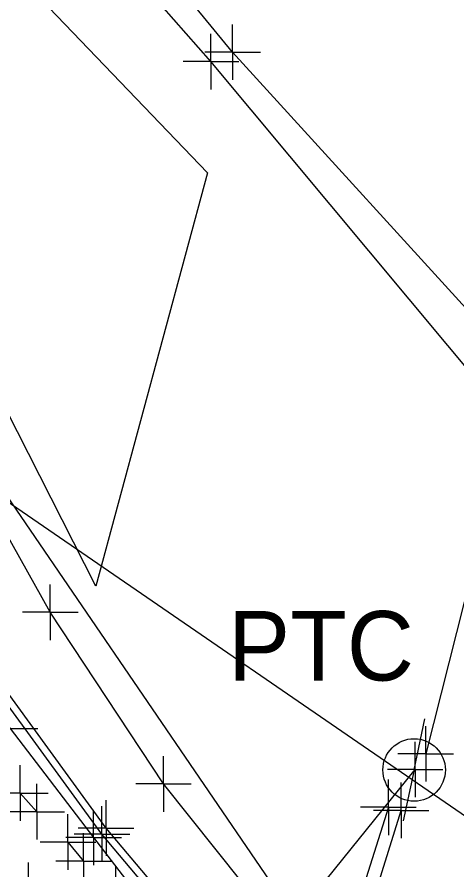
# Model space of a CAD drawing. Extents: x 0 to 1944463, y 0 to 420651.
# Drawn here: x 1943092.9 to 1943124.6, y 417632.9 to 417694.3 of the extents above; entities that cross this region are included whole.
import ezdxf

# ---------------------------------------------------------------- set-up
doc = ezdxf.new("R2010")
doc.units = 0
for name, color, linetype in [('SUR - DRG - Bridges', 7, 'Continuous'), ('SUR - DRG - Bridges - Points - Locators', 7, 'Continuous'), ('SUR - DRG - Storm Sewer', 7, 'Continuous'), ('SUR - DTM - Breaklines', 7, 'Continuous'), ('SUR - DTM - Breaklines - Points - Locators', 7, 'Continuous'), ('SUR - NON-TRAN - Features', 7, 'Continuous'), ('SUR - NON-TRAN - Features - Points - Locators', 7, 'Continuous'), ('SUR - TR-CTRL - Pavement Marking', 7, 'Continuous'), ('SUR - TR-CTRL - Pavement Marking - Points - Locators', 7, 'Continuous'), ('SUR - TRAN - Features', 7, 'Continuous'), ('SUR - TRAN - Features - Points - Locators', 7, 'Continuous'), ('SUR - UTL - Overhead Wire Crossings', 7, 'Continuous'), ('SUR - UTL - Overhead Wire Crossings - Points - Locators', 7, 'Continuous'), ('SUR - UTL - Poles and Miscellaneous', 7, 'Continuous'), ('SUR - UTL - Poles and Miscellaneous Text', 7, 'Continuous'), ('SUR - VEG - Features', 7, 'Continuous')]:
    doc.layers.add(name, color=color, linetype=linetype)

msp = doc.modelspace()

# ---------------------------------------------------------------- linework, layer by layer
at = {"layer": 'SUR - DRG - Bridges'}
msp.add_lwpolyline([(1943118.022, 417624.072), (1943118.566, 417626.015), (1943117.262, 417626.592), (1943120.565, 417637.227)], dxfattribs=at)
at = {"layer": 'SUR - DRG - Bridges - Points - Locators'}
for q in [(1943120.565, 417639.227), (1943118.565, 417637.227), (1943122.565, 417637.227), (1943120.565, 417635.227)]:
    msp.add_line((1943120.565, 417637.227), q, dxfattribs=at)
at = {"layer": 'SUR - DRG - Storm Sewer'}
msp.add_lwpolyline([(1942946.03, 417759.83), (1943172.9, 417604.06)], dxfattribs=at)
at = {"layer": 'SUR - DTM - Breaklines'}
for points in [[(1943113.816, 417618.747), (1943099.312, 417635.958), (1943090.009, 417648.721), (1943077.226, 417667.859), (1943069.186, 417677.24), (1943048.744, 417697.336), (1943014.67, 417728.445), (1942991.453, 417748.17), (1942972.688, 417763.041), (1942938.864, 417788.284), (1942937.547, 417790.234), (1942937.458, 417791.641), (1942938.043, 417793.096)], [(1943148.594, 417595.6), (1943148.623, 417618.666), (1943148.003, 417634.848), (1943135.154, 417656.915), (1943126.831, 417667.186), (1943106.868, 417691.105), (1943092.646, 417707.26), (1943066.336, 417736.048), (1943052.909, 417761.604)], [(1943088.753, 417664.788), (1943115.13, 417626.235)], [(1943119.642, 417637.454), (1943116.27, 417626.76), (1943116, 417625.717)]]:
    msp.add_lwpolyline(points, dxfattribs=at)
at = {"layer": 'SUR - DTM - Breaklines - Points - Locators'}
for p, q in [((1943106.868, 417691.105), (1943106.868, 417693.105)), ((1943106.868, 417691.105), (1943104.868, 417691.105)), ((1943106.868, 417691.105), (1943108.868, 417691.105)), ((1943106.868, 417691.105), (1943106.868, 417689.105)), ((1943119.642, 417637.454), (1943119.642, 417639.454)), ((1943099.312, 417635.958), (1943099.312, 417637.958)), ((1943119.642, 417637.454), (1943117.642, 417637.454)), ((1943119.642, 417637.454), (1943121.642, 417637.454)), ((1943119.642, 417637.454), (1943119.642, 417635.454)), ((1943099.312, 417635.958), (1943097.312, 417635.958)), ((1943099.312, 417635.958), (1943101.312, 417635.958)), ((1943099.312, 417635.958), (1943099.312, 417633.958))]:
    msp.add_line(p, q, dxfattribs=at)
at = {"layer": 'SUR - NON-TRAN - Features'}
msp.add_lwpolyline([(1943149.246, 417640.467), (1943127.93, 417670.388), (1943108.427, 417691.782), (1943094.662, 417708.534), (1943067.517, 417736.864), (1943051.792, 417767.307)], dxfattribs=at)
at = {"layer": 'SUR - NON-TRAN - Features - Points - Locators'}
for q in [(1943108.427, 417693.782), (1943106.427, 417691.782), (1943110.427, 417691.782), (1943108.427, 417689.782)]:
    msp.add_line((1943108.427, 417691.782), q, dxfattribs=at)
at = {"layer": 'SUR - TR-CTRL - Pavement Marking'}
for points in [[(1943067.842, 417675.554), (1943072.492, 417670.044), (1943077.052, 417664.145), (1943082.9, 417656.286), (1943088.643, 417648.1), (1943089.12, 417647.42), (1943092.412, 417643.122), (1943098.42, 417635.279), (1943103.018, 417629.276)], [(1943093.135, 417638.475), (1943094.325, 417637.129)], [(1943096.572, 417634.95), (1943097.7, 417633.578)]]:
    msp.add_lwpolyline(points, dxfattribs=at)
at = {"layer": 'SUR - TR-CTRL - Pavement Marking - Points - Locators'}
for p, q in [((1943092.412, 417643.122), (1943094.412, 417643.122)), ((1943093.135, 417638.475), (1943093.135, 417640.475)), ((1943094.325, 417637.129), (1943094.325, 417639.129)), ((1943093.135, 417638.475), (1943091.135, 417638.475)), ((1943093.135, 417638.475), (1943095.135, 417638.475)), ((1943093.135, 417638.475), (1943093.135, 417636.475)), ((1943094.325, 417637.129), (1943092.325, 417637.129)), ((1943094.325, 417637.129), (1943096.325, 417637.129)), ((1943094.325, 417637.129), (1943094.325, 417635.129)), ((1943096.572, 417634.95), (1943096.572, 417636.95)), ((1943098.42, 417635.279), (1943098.42, 417637.279)), ((1943098.42, 417635.279), (1943096.42, 417635.279)), ((1943097.7, 417633.578), (1943097.7, 417635.578)), ((1943098.42, 417635.279), (1943100.42, 417635.279)), ((1943098.42, 417635.279), (1943098.42, 417633.279)), ((1943096.572, 417634.95), (1943094.572, 417634.95)), ((1943096.572, 417634.95), (1943098.572, 417634.95)), ((1943096.572, 417634.95), (1943096.572, 417632.95)), ((1943093.738, 417631.474), (1943093.738, 417633.474)), ((1943097.7, 417633.578), (1943095.7, 417633.578)), ((1943097.7, 417633.578), (1943099.7, 417633.578)), ((1943097.7, 417633.578), (1943097.7, 417631.578)), ((1943100.016, 417631.23), (1943100.016, 417633.23))]:
    msp.add_line(p, q, dxfattribs=at)
at = {"layer": 'SUR - TRAN - Features'}
for points in [[(1943114.834, 417624.896), (1943103.453, 417639.126), (1943095.3, 417651.485), (1943083.428, 417672.654), (1943076.721, 417682.249), (1943055.252, 417704.387), (1943020.966, 417735.536), (1942996.784, 417756.051), (1942978.451, 417770.697), (1942923.479, 417810.417), (1942907.463, 417821.141), (1942884.283, 417835.758), (1942865.83, 417846.651), (1942848.31, 417856.509), (1942835.5, 417863.859), (1942826.295, 417870.821), (1942818.403, 417877.862), (1942796.294, 417899.443), (1942790.861, 417907.343), (1942782.321, 417924.544), (1942774.775, 417947.78), (1942772.79, 417958.555), (1942771.547, 417970.782), (1942773.585, 418011.209)], [(1943113.532, 417618.282), (1943099.019, 417635.522), (1943089.665, 417648.289), (1943076.796, 417667.519), (1943068.854, 417676.896), (1943048.284, 417697.021), (1943014.345, 417728.006), (1942991.136, 417747.722), (1942972.347, 417762.672), (1942938.609, 417787.801), (1942937.085, 417790.006), (1942936.962, 417791.695), (1942937.622, 417793.339)]]:
    msp.add_lwpolyline(points, dxfattribs=at)
at = {"layer": 'SUR - TRAN - Features - Points - Locators'}
for p, q in [((1943095.3, 417651.485), (1943095.3, 417653.485)), ((1943095.3, 417651.485), (1943093.3, 417651.485)), ((1943095.3, 417651.485), (1943097.3, 417651.485)), ((1943095.3, 417651.485), (1943095.3, 417649.485)), ((1943103.453, 417639.126), (1943103.453, 417641.126)), ((1943103.453, 417639.126), (1943101.453, 417639.126)), ((1943103.453, 417639.126), (1943105.453, 417639.126)), ((1943103.453, 417639.126), (1943103.453, 417637.126)), ((1943099.019, 417635.522), (1943099.019, 417637.522)), ((1943099.019, 417635.522), (1943097.019, 417635.522)), ((1943099.019, 417635.522), (1943101.019, 417635.522)), ((1943099.019, 417635.522), (1943099.019, 417633.522))]:
    msp.add_line(p, q, dxfattribs=at)
at = {"layer": 'SUR - UTL - Overhead Wire Crossings'}
for points in [[(1943170.286, 417830.891), (1943122.328, 417641.294)], [(1943055.95, 417558.92), (1943121.57, 417640.17)]]:
    msp.add_lwpolyline(points, dxfattribs=at)
at = {"layer": 'SUR - UTL - Overhead Wire Crossings - Points - Locators'}
for p, q in [((1943122.328, 417641.294), (1943122.328, 417643.294)), ((1943121.57, 417640.17), (1943121.57, 417642.17)), ((1943122.328, 417641.294), (1943120.328, 417641.294)), ((1943122.328, 417641.294), (1943124.328, 417641.294)), ((1943122.328, 417641.294), (1943122.328, 417639.294)), ((1943121.57, 417640.17), (1943119.57, 417640.17)), ((1943121.57, 417640.17), (1943123.57, 417640.17)), ((1943121.57, 417640.17), (1943121.57, 417638.17))]:
    msp.add_line(p, q, dxfattribs=at)
at = {"layer": 'SUR - UTL - Poles and Miscellaneous'}
for q in [(1943122.277, 417643.804), (1943120.717, 417636.468)]:
    msp.add_line((1943121.497, 417640.136), q, dxfattribs=at)
msp.add_circle((1943121.497, 417640.136), 2.25, dxfattribs=at)
at = {"layer": 'SUR - VEG - Features'}
msp.add_lwpolyline([(1943106.621, 417683.089), (1943098.581, 417653.35), (1943082.421, 417685.101), (1943028.095, 417749.727), (1943043.243, 417819.273), (1943053.355, 417815.961), (1943045.898, 417762.473), (1943062.652, 417728.878)], close=True, dxfattribs=at)

# ---------------------------------------------------------------- texts
at = {"layer": 'SUR - UTL - Poles and Miscellaneous Text'}
msp.add_text('PTC', height=5, dxfattribs=at).set_placement((1943108.106, 417646.57))

doc.saveas('drawing.dxf')
